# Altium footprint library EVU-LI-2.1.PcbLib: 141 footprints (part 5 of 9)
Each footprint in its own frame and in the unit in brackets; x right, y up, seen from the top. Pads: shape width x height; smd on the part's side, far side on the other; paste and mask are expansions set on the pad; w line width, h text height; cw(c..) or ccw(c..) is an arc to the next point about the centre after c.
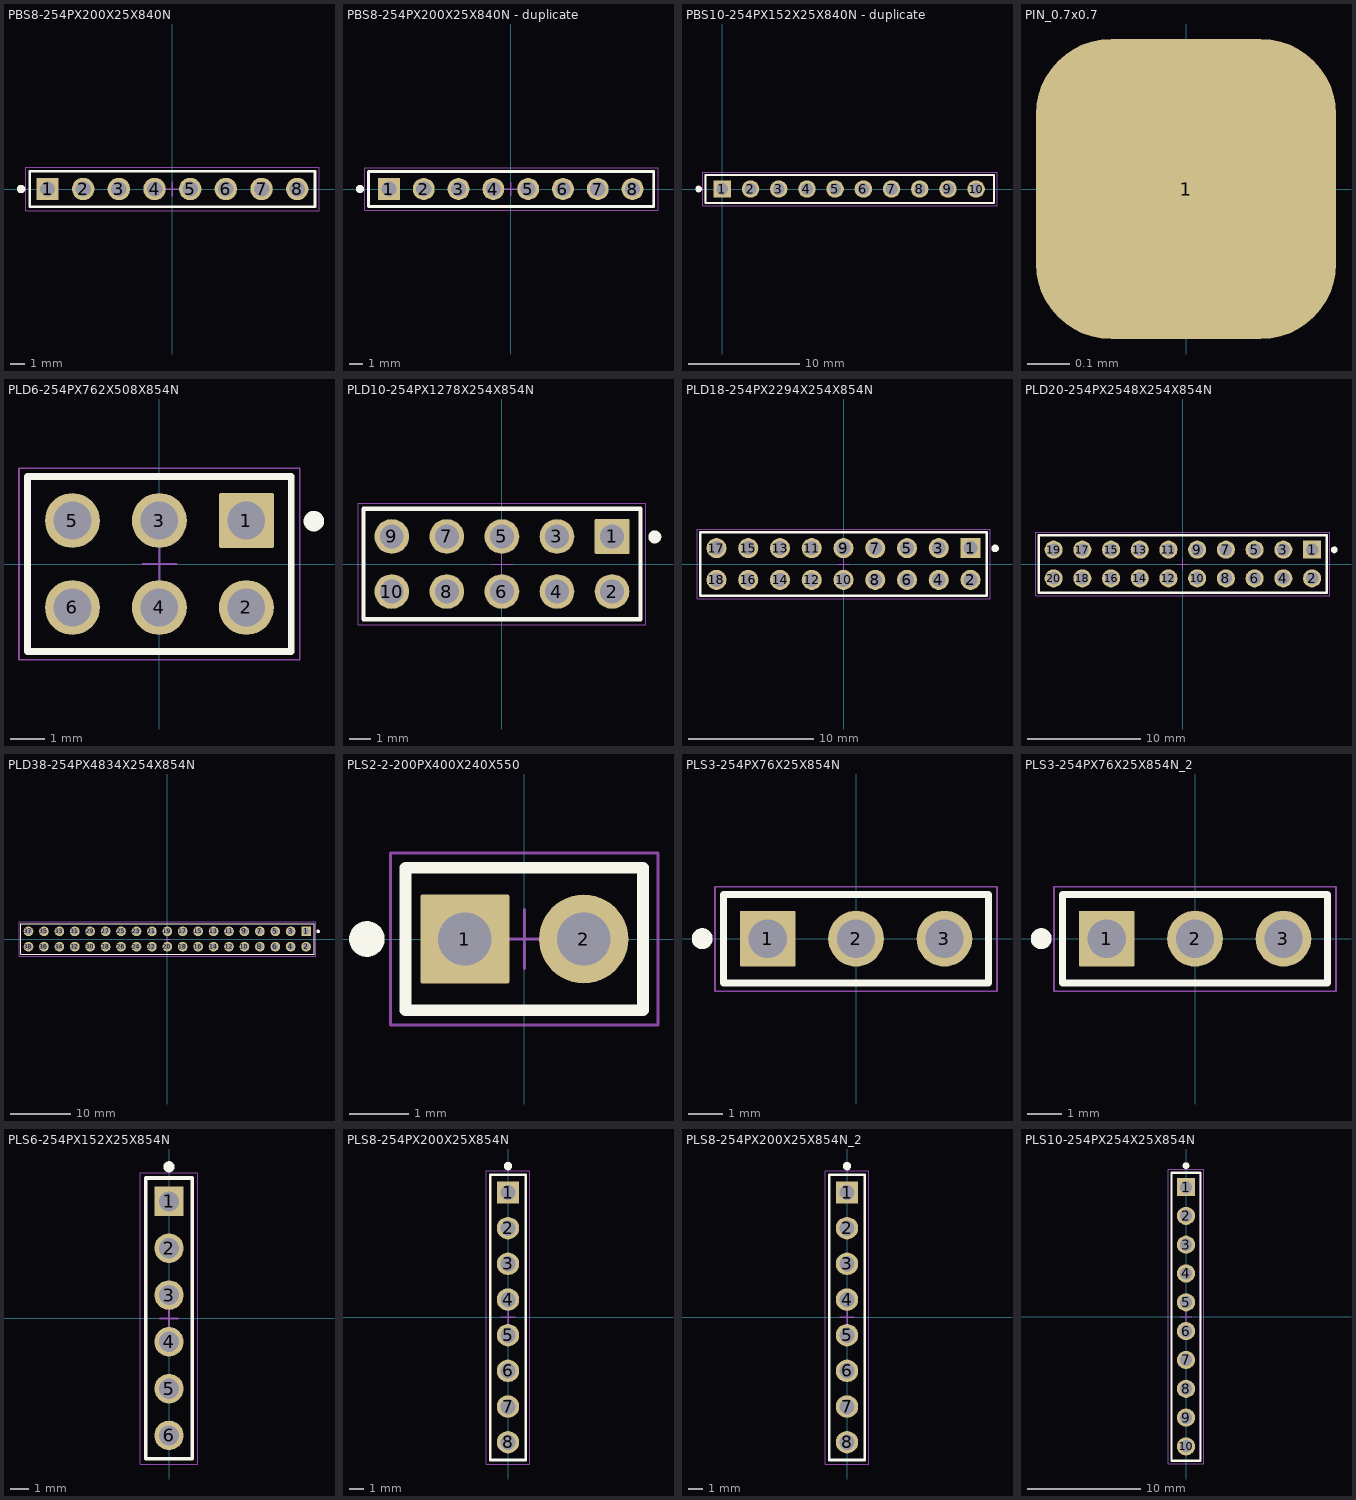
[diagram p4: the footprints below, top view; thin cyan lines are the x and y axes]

## PBS8-254PX200X25X840N [mil]
height 330.71
pads (8):
  rrect5% 63x63 hole 43.31 mask+2.76: 1(-350,0)
  round 63 hole 43.31 mask+2.76: 2(-250,0) 3(-150,0) 4(-50,0) 5(50,0) 6(150,0) 7(250,0) 8(350,0)
Top Overlay:
  circle w11.81: c-424.02,0 r5.91
  lines w7.87: -400,-50 400,-50 400,50 -400,50 -400,-50
Bottom Overlay:
  circle w11.81: c-400,50 r5.91
Top Assembly:
  lines w3.94: -400,-50 400,-50 400,50 -400,50 -400,-50
  text "1" at -426.57,-15.55 h59.06
Top Designator:
  text ".Designator" at 127.95,11.81 h59.06
Top Courtyard:
  lines w1.97: -411.02,-61.02 411.02,-61.02 411.02,61.02 -411.02,61.02 -411.02,-61.02
  lines w3.94: -19.68,0 19.68,0 ; 0,-19.68 0,19.68
3D body "PBS-8.STEP": height 330.71, standoff -125.98, extent -400,-50 400,50

## PBS8-254PX200X25X840N - duplicate [mil]
height 330.71
pads (8):
  rrect5% 63x63 hole 43.31 mask+2.76: 1(-350,0)
  round 63 hole 43.31 mask+2.76: 2(-250,0) 3(-150,0) 4(-50,0) 5(50,0) 6(150,0) 7(250,0) 8(350,0)
Top Overlay:
  circle w11.81: c-433,0 r5.91
  lines w7.87: -409,-50 411,-50 411,50 -409,50 -409,-50
Bottom Overlay:
  circle w11.81: c-409,50 r5.91
Top Assembly:
  lines w3.94: -409,-50 410,-50 410,50 -409,50 -409,-50
  text "1" at -426.57,-15.55 h59.06
Top Designator:
  text ".Designator" at 127.95,11.81 h59.06
Top Courtyard:
  lines w1.97: -419,-61.02 423,-61.02 423,61.02 -419,61.02 -419,-61.02
  lines w3.94: -19.68,0 19.68,0 ; 0,-19.68 0,19.68
3D body "PBS-8.step": height 334.65, standoff -118.11, extent -409.84,-49.21 409.84,49.21

## PBS10-254PX152X25X840N - duplicate [mm]
height 1.27
pads (10):
  rect 1.575x1.575 hole 1.05: 1(0,0)
  round 1.575 hole 1.05: 2(2.54,0) 3(5.08,0) 4(7.62,0) 5(10.16,0) 6(12.7,0) 7(15.24,0) 8(17.78,0) 9(20.32,0) 10(22.86,0)
Top Overlay:
  circle w0.3: c-2.134,0 r0.15
  lines w0.2: -1.52,-1.27 -1.52,1.27 24.46,1.27 24.46,-1.27 -1.473,-1.27
Bottom Overlay:
  circle w0.3: c-1.52,1.27 r0.15
Assembly Notes:
  lines w0.1: -1.52,-1.27 -1.52,1.27 24.46,1.27 24.46,-1.27 -1.52,-1.27
Top Courtyard:
  lines w0.05: -1.77,-1.52 -1.77,1.52 24.74,1.52 24.74,-1.52 -1.77,-1.52
3D body "PBS-10.step": height 8.5, standoff -3, extent -1.52,-1.25 24.38,1.25

## PIN_0.7x0.7 [mm]
pads (1):
  rrect50% 0.7x0.7 smd paste-2: 1(0,0)

## PLD6-254PX762X508X854N [mil]
pads (6):
  rrect5% 63x63 hole 43.31 mask+2.76: 1(100,50)
  round 63 hole 43.31 mask+2.76: 2(100,-50) 3(0,50) 4(0,-50) 5(-100,50) 6(-100,-50)
Top Overlay:
  circle w11.81: c177.56,49.21 r5.91
  lines w7.87: -151.57,-100.39 151.57,-100.39 151.57,100.39 -151.57,100.39 -151.57,-100.39
Top Assembly:
  lines w3.94: -151.57,-100.39 151.57,-100.39 151.57,100.39 -151.57,100.39 -151.57,-100.39
  text "2" at 173.03,-68.9 h59.06
  text "1" at 173.03,37.4 h59.06
Top Designator:
  text ".Designator" at -127.95,-11.81 h59.06
Top Courtyard:
  lines w1.97: -19.68,0 19.68,0 ; 0,-19.68 0,19.68 ; -161.42,-110.24 161.42,-110.24 161.42,110.24 -161.42,110.24 -161.42,-110.24
3D body "PLD-6.STEP": height 336.22, standoff 0, extent -150,-100 150,100

## PLD10-254PX1278X254X854N [mil]
pads (10):
  rrect5% 63x63 hole 43.31 mask+2.76: 1(200,50)
  round 63 hole 43.31 mask+2.76: 2(200,-50) 3(100,50) 4(100,-50) 5(0,50) 6(0,-50) 7(-100,50) 8(-100,-50) 9(-200,50) 10(-200,-50)
Top Overlay:
  circle w11.81: c277.56,49.21 r5.91
  lines w7.87: -251.57,-100.39 -251.57,100.39 251.57,100.39 251.57,-100.39 -251.57,-100.39
Top Assembly:
  lines w3.94: -251.57,-100.39 -251.57,100.39 251.57,100.39 251.57,-100.39 -251.57,-100.39
  text "2" at 273.03,-68.9 h59.06
  text "1" at 273.03,37.4 h59.06
Top Designator:
  text ".Designator" at -127.95,-11.81 h59.06
Top Courtyard:
  lines w1.97: -19.68,0 19.68,0 ; 0,-19.68 0,19.68 ; -261.42,-110.24 -261.42,110.24 261.42,110.24 261.42,-110.24 -261.42,-110.24
3D body "PLD-10.STEP": height 336.22, standoff 0, extent -250,-100 250,100

## PLD18-254PX2294X254X854N [mil]
pads (18):
  rrect5% 63x63 hole 43.31 mask+2.76: 1(400,50)
  round 63 hole 43.31 mask+2.76: 2(400,-50) 3(300,50) 4(300,-50) 5(200,50) 6(200,-50) 7(100,50) 8(100,-50) 9(0,50) 10(0,-50) 11(-100,50) 12(-100,-50) 13(-200,50) 14(-200,-50) 15(-300,50) 16(-300,-50) 17(-400,50) 18(-400,-50)
Top Overlay:
  circle w11.81: c477.56,49.21 r5.91
  lines w7.87: -451.57,-100.39 -451.57,100.39 451.57,100.39 451.57,-100.39 -451.57,-100.39
Bottom Overlay:
  circle w11.81: c451.57,100.39 r5.91
Top Assembly:
  text "2" at 473.03,-68.9 h59.06
  text "1" at 473.03,37.4 h59.06
Top Designator:
  text ".Designator" at -127.95,-11.81 h59.06
Top Courtyard:
  lines w1.97: -19.68,0 19.68,0 ; 0,-19.68 0,19.68 ; -461.42,-110.24 461.42,-110.24 461.42,110.24 -461.42,110.24 -461.42,-110.24
3D body "PLD-18.STEP": height 336.22, standoff 0, extent -450,-100 450,100

## PLD20-254PX2548X254X854N [mil]
pads (20):
  rrect5% 63x63 hole 43.31 mask+2.76: 1(450,50)
  round 63 hole 43.31 mask+2.76: 2(450,-50) 3(350,50) 4(350,-50) 5(250,50) 6(250,-50) 7(150,50) 8(150,-50) 9(50,50) 10(50,-50) 11(-50,50) 12(-50,-50) 13(-150,50) 14(-150,-50) 15(-250,50) 16(-250,-50) 17(-350,50) 18(-350,-50) 19(-450,50) 20(-450,-50)
Top Overlay:
  circle w11.81: c527.56,49.21 r5.91
  lines w7.87: -501.57,-100.39 -501.57,100.39 501.57,100.39 501.57,-100.39 -501.57,-100.39
Bottom Overlay:
  circle w11.81: c501.57,100.39 r5.91
Top Assembly:
  text "1" at 523.03,37.4 h59.06
  text "2" at 523.03,-68.9 h59.06
Top Designator:
  text ".Designator" at -127.95,-11.81 h59.06
Top Courtyard:
  lines w1.97: -19.68,0 19.68,0 ; 0,-19.68 0,19.68 ; -511.42,-110.24 -511.42,110.24 511.42,110.24 511.42,-110.24 -511.42,-110.24
3D body "PLD-20.STEP": height 336.22, standoff 0, extent -500,-100 500,100

## PLD38-254PX4834X254X854N [mil]
pads (38):
  rrect5% 63x63 hole 43.31 mask+2.76: 1(900,50)
  round 63 hole 43.31 mask+2.76: 2(900,-50) 3(800,50) 4(800,-50) 5(700,50) 6(700,-50) 7(600,50) 8(600,-50) 9(500,50) 10(500,-50) 11(400,50) 12(400,-50) 13(300,50) 14(300,-50) 15(200,50) 16(200,-50) 17(100,50) 18(100,-50) 19(0,50) 20(0,-50) 21(-100,50) 22(-100,-50) 23(-200,50) 24(-200,-50) 25(-300,50) 26(-300,-50) 27(-400,50) 28(-400,-50) 29(-500,50) 30(-500,-50) 31(-600,50) 32(-600,-50) 33(-700,50) 34(-700,-50) 35(-800,50) 36(-800,-50) 37(-900,50) 38(-900,-50)
Top Overlay:
  circle w11.81: c977.56,49.21 r5.91
  lines w7.87: -951.57,-100.39 -951.57,100.39 951.57,100.39 951.57,-100.39 -951.57,-100.39
Bottom Overlay:
  circle w11.81: c951.57,100.39 r5.91
Top Assembly:
  text "2" at 973.03,-68.9 h59.06
  text "1" at 973.03,37.4 h59.06
Top Designator:
  text ".Designator" at -137.8,-11.81 h59.06
Top Courtyard:
  lines w1.97: -19.68,0 19.68,0 ; 0,-19.68 0,19.68 ; -961.42,-110.24 -961.42,110.24 961.42,110.24 961.42,-110.24 -961.42,-110.24
3D body "PLD-38.STEP": height 336.22, standoff 0, extent -950,-100 950,100

## PLS2-2-200PX400X240X550 [mm]
pads (2):
  rrect5% 1.5x1.5 hole 0.9 mask+0.07: 1(-1,0)
  round 1.5 hole 0.9 mask+0.07: 2(1,0)
Top Overlay:
  circle w0.3: c-2.65,0 r0.15
  lines w0.2: -2,-1.2 2,-1.2 2,1.2 -2,1.2 -2,-1.2
Mechanical 1:
  lines w0.1: -2,-1.2 2,-1.2 2,1.2 -2,1.2 -2,-1.2
  text "1" at -2.945,-0.395 h1.5
  text ".Designator" at -3.25,-0.3 h1.5
Top Courtyard:
  lines w0.05: -0.5,0 0.5,0 ; 0,-0.5 0,0.5 ; -2.25,-1.45 2.25,-1.45 2.25,1.45 -2.25,1.45 -2.25,-1.45
3D body "PLS2-2.STEP": height 5.5, standoff -2.5, extent -2,-1.2 2,1.2

## PLS3-254PX76X25X854N [mil]
pads (3):
  rrect5% 63x63 hole 43.31 mask+2.76: 1(-100,0)
  round 63 hole 43.31 mask+2.76: 2(0,0) 3(100,0)
Top Overlay:
  circle w11.81: c-174.02,0 r5.91
  lines w7.87: -150,-50 150,-50 150,50 -150,50 -150,-50
Top Assembly:
  lines w3.94: -150,-50 150,-50 150,50 -150,50 -150,-50
  text "1" at -176.57,-15.55 h59.06
Top Designator:
  text ".Designator" at -127.95,-11.81 h59.06
Top Courtyard:
  lines w1.97: -159.45,-59.45 159.45,-59.45 159.45,58.66 -159.45,58.66 -159.45,-59.45 ; -19.68,0 19.68,0 -19.68,0 ; 0,-19.68 0,19.68 0,-19.68
3D body "PLS-3.STEP": height 336.22, standoff 0, extent -150,-50 150,50

## PLS3-254PX76X25X854N_2 [mil]
pads (3):
  rrect5% 63x63 hole 43.31 mask+2.76: 1(-100,0)
  round 63 hole 43.31 mask+2.76: 2(0,0) 3(100,0)
Top Overlay:
  circle w11.81: c-174.02,0 r5.91
  lines w7.87: -150,-50 150,-50 150,50 -150,50 -150,-50
Top Assembly:
  lines w3.94: -150,-50 150,-50 150,50 -150,50 -150,-50
  text "1" at -176.57,-15.55 h59.06
Top Designator:
  text ".Designator" at -127.95,-11.81 h59.06
Top Courtyard:
  lines w1.97: -159.45,-59.45 159.45,-59.45 159.45,58.66 -159.45,58.66 -159.45,-59.45 ; -19.68,0 19.68,0 -19.68,0 ; 0,-19.68 0,19.68 0,-19.68
3D body "PLS-3.STEP": height 336.22, standoff 0, extent -150,-50 150,50

## PLS6-254PX152X25X854N [mil]
pads (6):
  rrect5% 63x63 hole 43.31 mask+2.76: 1(0,250)
  round 63 hole 43.31 mask+2.76: 2(0,150) 3(0,50) 4(0,-50) 5(0,-150) 6(0,-250)
Top Overlay:
  circle w11.81: c0,324.02 r5.91
  lines w7.87: -50,-300 -50,300 50,300 50,-300 -50,-300
Bottom Overlay:
  circle w11.81: c0,324.02 r5.91
Mechanical 1:
  lines w3.94: -50,-300 -50,300 50,300 50,-300 -50,-300
  text "1" at -15.55,326.57 h59.06
  text ".Designator" at 11.81,-127.95 h59.06
Top Courtyard:
  lines w1.97: -61.02,-311.02 -61.02,311.02 61.02,311.02 61.02,-311.02 -61.02,-311.02
  lines w3.94: -19.68,0 19.68,0 ; 0,-19.68 0,19.68
3D body "PLS-6.STEP": height 336.22, standoff 0, extent -49.99,-299.99 50.01,300.01

## PLS8-254PX200X25X854N [mil]
pads (8):
  rrect5% 63x63 hole 43.31 mask+2.76: 1(0,350)
  round 63 hole 43.31 mask+2.76: 2(0,250) 3(0,150) 4(0,50) 5(0,-50) 6(0,-150) 7(0,-250) 8(0,-350)
Top Overlay:
  circle w11.81: c0,424.02 r5.91
  lines w7.87: -50,-400 50,-400 50,400 -50,400 -50,-400
Bottom Overlay:
  circle w11.81: c50,400 r5.91
Mechanical 1:
  lines w3.94: -50,-400 50,-400 50,400 -50,400 -50,-400
  text "1" at -15.55,426.57 h59.06
  text ".Designator" at 11.81,-127.95 h59.06
Top Courtyard:
  lines w1.97: -61.02,-411.02 61.02,-411.02 61.02,411.02 -61.02,411.02 -61.02,-411.02
  lines w3.94: -19.68,0 19.68,0 ; 0,-19.68 0,19.68
3D body "PLS-8.STEP": height 336.22, standoff 0, extent -49.99,-399.99 50.01,400.01

## PLS8-254PX200X25X854N_2 [mil]
pads (8):
  rrect5% 63x63 hole 43.31 mask+2.76: 1(0,350)
  round 63 hole 43.31 mask+2.76: 2(0,250) 3(0,150) 4(0,50) 5(0,-50) 6(0,-150) 7(0,-250) 8(0,-350)
Top Overlay:
  circle w11.81: c0,424.02 r5.91
  lines w7.87: -50,-400 50,-400 50,400 -50,400 -50,-400
Bottom Overlay:
  circle w11.81: c0,424.02 r5.91
Top Assembly:
  lines w3.94: -50,-400 50,-400 50,400 -50,400 -50,-400
  text "1" at -15.55,426.57 h59.06
Top Designator:
  text ".Designator" at 11.81,-127.95 h59.06
Top Courtyard:
  lines w1.97: -61.02,-411.02 61.02,-411.02 61.02,411.02 -61.02,411.02 -61.02,-411.02
  lines w3.94: -19.68,0 19.68,0 ; 0,-19.68 0,19.68
3D body "PLS-8.STEP": height 336.22, standoff 0, extent -50,-400 50,400

## PLS10-254PX254X25X854N [mil]
pads (10):
  rrect5% 63x63 hole 43.31 mask+2.76: 1(0,450)
  round 63 hole 43.31 mask+2.76: 2(0,350) 3(0,250) 4(0,150) 5(0,50) 6(0,-50) 7(0,-150) 8(0,-250) 9(0,-350) 10(0,-450)
Top Overlay:
  circle w11.81: c0,524.02 r5.91
  lines w7.87: -50,-500 -50,500 50,500 50,-500 -50,-500
Bottom Overlay:
  circle w11.81: c0,524.02 r5.91
Mechanical 1:
  lines w3.94: -50,-500 -50,500 50,500 50,-500 -50,-500
  text "1" at -15.55,526.57 h59.06
  text ".Designator" at 11.81,-127.95 h59.06
Top Courtyard:
  lines w1.97: -61.02,-511.02 -61.02,511.02 61.02,511.02 61.02,-511.02 -61.02,-511.02
  lines w3.94: -19.68,0 19.68,0 ; 0,-19.68 0,19.68
3D body "PLS-10.STEP": height 336.22, standoff 0, extent -49.99,-499.99 50.01,500.01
